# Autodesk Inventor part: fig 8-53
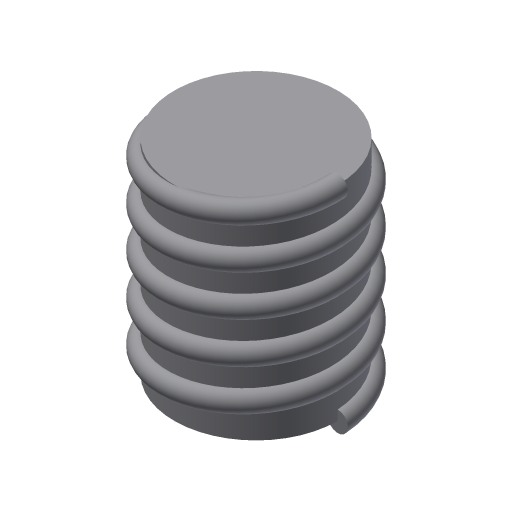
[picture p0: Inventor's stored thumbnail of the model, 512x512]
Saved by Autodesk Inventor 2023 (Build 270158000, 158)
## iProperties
Created: 2002-01
Part Number: fig 8-53
Document SubType Name: Modeling
Designer: CADSoft
Density: 1 g/cm^3
Material: Generic
Appearance: Default
Control State: 0
Master: False
Checked Out: False
Shininess: 77.0
Length Units: 11269
Angle Units: 11279
Time Units: 11290
Mass Units: 11283
Length Display Precision: 3
Angle Display Precision: 2
Density: 0.0
Volumn: 0.0
Area: 0.0
PropertySet Name: Model Information
Author: CADSoft
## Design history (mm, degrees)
sketch "Sketch4"
  geometry: C1 r 20 at (0, 0)
  constraints: 1 centre point
  dimensions: "d44" = 40 diameter of C1
sketch "Sketch2"
  geometry: C1 r 2.5 at (-20, -0.092); 1 further point
  constraints: 1 centre point, 1 other
  dimensions: "d0" = 5 diameter of C1; "d43" = 20 horizontal distance of C1.centre point (0, 0)
extrude "Extrusion2" join sketch "Sketch4" distance "d45" = 50; taper "d46" = 0 deg
coil "Coil6" pitch "d47" = 10; turns "d49" = 5; dims "d48" = 10, "d50" = 0, angle "d51" = 90 deg, angle "d52" = 90 deg, "d53" = 0, "d54" = 0
body "Solid1"
